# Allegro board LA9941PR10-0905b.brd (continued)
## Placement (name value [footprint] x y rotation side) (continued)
PC270  -  [C_0402]  100.14 24.35 0 bottom
PC271  -  [C_0402]  66.08 23.15 180 top
PC301  -  [C_0402]  48.17 37.17 270 top
PC302  -  [C_0402]  51.47 36.26 90 top
PC303  -  [C_0402]  41.82 22.57 270 bottom
PC304  -  [C_0402]  42.71 22.57 270 bottom
PC305  -  [C_0805]  42.33 22.45 270 top
PC306  -  [C_0402]  43.73 22.57 270 bottom
PC307  -  [C_0603]  49.31 35.89 90 top
PC308  -  [C_0402]  44.62 22.57 270 bottom
PC309  -  [C_0805]  44.11 22.45 270 top
PC310  -  [C_0603]  44.68 32.17 180 top
PC311  -  [C_0603]  54.33 31.25 180 top
PC312  -  [C_B2]  33.92 20.01 90 top
PC313  -  [C_B2]  59.02 21.19 90 bottom
PC314  -  [C_0402]  44.49 16.7 90 top
PC315  -  [C_0402]  41.82 19.14 270 top
PC316  -  [C_0603]  39.03 27.13 270 bottom
PC317  -  [C_0603]  47.47 25.67 180 bottom
PC319  -  [C_0603]  48.92 28.74 0 top
PC320  -  [C_0402]  47.79 29.3 270 top
PC340  -  [C_0402]  45.53 22.57 270 bottom
PC400  -  [C_0805]  130.39 15.3 270 bottom
PC401  -  [C_0805]  130.39 15.3 270 top
PC402  -  [C_0402]  129.07 14.74 270 top
PC403  -  [C_0402]  129.07 14.74 270 bottom
PC404  -  [C_0603]  126.81 14.68 90 bottom
PC405  -  [C_0805]  125.64 21.08 90 bottom
PC406  -  [C_0805]  126.28 20.97 90 top
PC407  -  [C_0603]  127.05 11.95 180 top
PC408  -  [C_B2]  143.57 15.12 90 bottom
PC409  -  [C_0603]  132.9 18.61 180 bottom
PC410  -  [C_0603]  123.61 13.34 270 top
PC411  -  [C_0402]  124.9 20.89 90 top
PC412  -  [C_0402]  121.28 19.87 90 top
PC500  -  [C_0402]  241.12 62.61 270 top
PC501  -  [C_0402]  242.04 62.61 270 top
PC502  -  [C_0805]  240.55 64.85 90 top
PC503  -  [C_0805]  244.29 63.2 90 top
PC504  -  [C_0603]  234.95 65.86 90 top
PC506  -  [C_0603]  232.79 68.59 270 top
PC507  -  [C_B2]  254.44 70.39 270 bottom
PC509  -  [C_0402]  245.4 68.03 180 top
PC510  -  [C_0402]  227.52 68.7 90 bottom
PC511  -  [C_0402]  242.93 62.61 270 top
PC600  -  [C_0402]  184.32 123.74 270 top
PC601  -  [C_0402]  184.21 123.78 270 bottom
PC602  -  [C_0402]  191.2 126.22 180 top
PC603  -  [C_0805]  185.61 123.92 270 top
PC604  -  [C_0603]  187.87 126.25 0 top
PC605  -  [C_0402]  191.37 123.71 0 top
PC607  -  [C_0603]  183.96 119.32 90 top
PC610  -  [C_0805]  185.61 123.92 270 bottom
PC611  -  [C_0805]  186.38 109.98 0 bottom
PC612  -  [C_0805]  186.38 111.69 0 bottom
PC613  -  [C_0805]  186.21 109.99 0 top
PC614  -  [C_0603]  190.56 120.85 270 top
PC620  -  [C_0402]  183.32 123.76 270 bottom
PC621  -  [C_0805]  187.36 123.9 270 top
PC700  -  [C_D2]  121.2 74.56 0 bottom
PC701  -  [C_0805]  112.94 108.05 270 bottom
PC702  -  [C_0805]  114.72 108.05 270 top
PC703  -  [C_0805]  112.94 108.05 270 top
PC704  -  [C_0402]  116.91 108.12 270 top
PC705  -  [C_0402]  116.04 108.12 270 top
PC706  -  [C_0603]  120.01 112.09 0 bottom
PC707  -  [C_0603]  113.28 102.43 90 bottom
PC708  -  [C_0603]  123.97 115.04 270 top
PC709  -  [C_0402]  123.97 121.75 270 bottom
PC710  -  [C_0402]  124.85 122.62 90 bottom
PC711  -  [C_0603]  125.21 113.61 90 top
PC714  -  [C_0603]  127.71 114.89 180 top
PC715  -  [C_0805]  116.24 72.95 90 top
PC716  -  [C_0805]  114.47 72.95 90 top
PC717  -  [C_0805]  118.02 72.95 90 top
PC718  -  [C_0402]  128.97 119.39 0 bottom
PC719  -  [C_0402]  119.42 73.15 90 top
PC721  -  [C_0402]  120.39 73.15 90 top
PC722  -  [C_0402]  128.97 115.65 0 bottom
PC724  -  [C_0402]  126.63 120.84 90 bottom
PC725  -  [C_0402]  128.01 122.96 270 bottom
PC726  -  [C_0402]  126.68 121.66 90 top
PC727  -  [C_0603]  124.78 109.8 90 bottom
PC728  -  [C_0603]  114.43 79.57 270 top
PC729  -  [C_0402]  129.88 113.87 180 bottom
PC730  -  [C_0603]  129.49 109.8 90 bottom
PC731  -  [C_0603]  128.22 109.8 90 bottom
PC732  -  [C_0402]  129.3 116.03 180 top
PC733  -  [C_0402]  127.82 118 270 top
PC734  -  [C_0402]  129.92 116.71 90 bottom
PC736  -  [C_0402]  128.97 117.62 270 bottom
PC737  -  [C_0402]  126.05 115.96 0 top
PC738  -  [C_0402]  126.96 117.11 180 top
PC761  -  [C_0402]  121.36 73.15 90 top
PC762  -  [C_0402]  117.79 108.12 270 top
PC800  -  [C_0603]  145.12 116.8 90 bottom
PC801  -  [C_0805]  153.73 122.78 270 top
PC802  -  [C_0805]  155.88 123.99 0 top
PC803  -  [C_0805]  155.88 122.06 0 top
PC804  -  [C_0805]  153.84 122.02 270 bottom
PC805  -  [C_0402]  152.33 121.88 270 top
PC806  -  [C_0402]  152.45 121.51 270 bottom
PC807  -  [C_0402]  140.04 122.06 0 top
PC809  -  [C_0603]  161.22 122.25 0 top
PC810  -  [C_0402]  140.07 120.91 0 top
PC811  -  [C_0402]  138.24 118.2 270 bottom
PC812  -  [C_0402]  142.37 120.07 90 top
PC813  -  [C_0603]  145.32 127.53 270 bottom
PC814  -  [C_0805]  164.76 126.21 270 top
PC815  -  [C_0805]  166.54 126.21 270 top
PC816  -  [C_0805]  164.76 126.21 270 bottom
PC817  -  [C_0805]  168.31 126.21 270 top
PC818  -  [C_0402]  163.37 126.2 270 bottom
PC819  -  [C_0402]  163.37 126.2 270 top
PC820  -  [C_0402]  136.5 120.35 270 bottom
PC821  -  [C_0402]  137.38 123.96 0 bottom
PC822  -  [C_0603]  169.2 120.73 90 top
PC823  -  [C_0603]  146.53 122.95 0 bottom
PC824  -  [C_0402]  137.38 125.87 0 bottom
PC825  -  [C_0402]  140.96 124.09 180 top
PC829  -  [C_B2]  180.53 113.68 90 bottom
PC830  -  [C_B2]  184.08 113.68 90 bottom
PC831  -  [C_B2]  180.62 117.94 180 bottom
PC832  -  [C_0805]  176.95 126.85 270 top
PC833  -  [C_0805]  173.39 126.85 270 bottom
PC834  -  [C_0805]  173.39 126.85 270 top
PC835  -  [C_0805]  175.17 126.85 270 top
PC836  -  [C_0402]  172 126.96 270 bottom
PC837  -  [C_0402]  172 126.96 270 top
PC838  -  [C_0603]  176.95 121.74 90 top
PC839  -  [C_0603]  182.41 127.71 270 top
PC850  -  [C_0402]  151.48 121.51 270 bottom
PC851  -  [C_0402]  162.43 126.2 270 top
PC852  -  [C_0402]  178.41 127.48 270 top
PC900  -  [C_0402]  154.35 96.05 0 top
PC901  -  [C_0402]  156.38 97.07 0 top
PC902  -  [C_0402]  156.38 98.08 0 top
PC903  -  [C_0402]  162.12 98.08 180 top
PC904  -  [C_0402]  152.32 97.07 0 top
PC905  -  [C_0402]  150.95 98.08 180 top
PC906  -  [C_0402]  159.33 98.08 180 top
PC907  -  [C_0402]  164.15 97.07 180 top
PC908  -  [C_0402]  152.32 96.05 0 top
PC909  -  [C_0402]  150.95 95.03 180 top
PC910  -  [C_0603]  217.02 89.67 0 top
PC911  -  [C_0603]  212 89.67 0 top
PC912  -  [C_0603]  213.53 91.96 180 top
PC913  -  [C_0603]  212.07 93.74 0 top
PC914  -  [C_0603]  213.46 95.77 180 top
PC915  -  [C_0603]  212.07 97.74 0 top
PC916  -  [C_0603]  214.61 89.67 0 top
PC917  -  [C_0603]  215.94 91.96 180 top
PC918  -  [C_0603]  214.48 93.74 0 top
PC919  -  [C_0603]  215.88 95.77 180 top
PC921  -  [C_D2]  129.26 90.73 90 bottom
PC922  -  [C_D2]  133.58 86.57 270 bottom
PC923  -  [C_D2]  144.92 113.88 180 bottom
PC924  -  [C_D2]  128.88 86.57 270 bottom
PC926  -  [C_0402]  152.32 98.08 0 top
PC927  -  [C_0402]  159.33 97.07 180 top
PC928  -  [C_0402]  168.09 97.07 180 top
PC929  -  [C_0402]  162.12 97.07 180 top
PC930  -  [C_0402]  153.47 82.81 0 top
PC931  -  [C_0402]  151.64 82.14 180 top
PC932  -  [C_0402]  156.38 96.05 0 top
PC933  -  [C_0402]  151.64 83.16 180 top
PC934  -  [C_0402]  172.15 97.07 180 top
PC935  -  [C_0402]  154.35 98.08 0 top
PC936  -  [C_0402]  216.97 95.77 0 top
PC937  -  [C_0402]  211.57 88.21 180 top
PC938  -  [C_0402]  218.31 97.59 90 top
PC939  -  [C_0402]  217.44 97.67 180 top
PC940  -  [C_0603]  212.89 87.58 270 top
PC941  -  [C_0603]  217.97 87.58 270 top
PC942  -  [C_0603]  215.43 87.58 270 top
PC943  -  [C_0603]  214.16 87.58 270 top
PC944  -  [C_0603]  216.7 87.58 270 top
PC953  -  [C_0805]  154.21 87.92 0 top
PC954  -  [C_0805]  154.21 85.89 0 top
PC955  -  [C_0805]  154.21 89.95 0 top
PC956  -  [C_0805]  159.77 85.74 180 top
PC958  -  [C_0805]  222.69 96.74 270 top
PC959  -  [C_0805]  222.41 89.99 90 top
PC961  -  [C_0805]  217.42 93.7 270 top
PC962  -  [C_0805]  219.23 91.14 0 top
PC963  -  [C_0805]  221.04 95.64 180 top
PC964  -  [C_0805]  219.37 98.05 0 top
PC965  -  [C_0805]  154.21 94.02 0 top
PC966  -  [C_0805]  154.21 91.99 0 top
PC967  -  [C_0805]  159.77 89.8 180 top
PC968  -  [C_0805]  165.05 86.78 180 top
PC969  -  [C_0805]  165.05 88.56 180 top
PC970  -  [C_0805]  168.53 94.63 180 top
PC971  -  [C_0805]  159.77 93.99 180 top
PC972  -  [C_0805]  165.05 85.07 180 top
PC973  -  [C_0805]  172.04 83.22 180 top
PC974  -  [C_0805]  165.05 90.59 180 top
PC975  -  [C_0805]  165.05 94.65 180 top
PC976  -  [C_0805]  165.05 92.62 180 top
PC977  -  [C_0805]  171.02 87.03 180 top
PC978  -  [C_0805]  171.02 88.94 180 top
PC979  -  [C_0805]  171.02 90.84 180 top
PC980  -  [C_0805]  172.04 92.75 180 top
PC981  -  [C_0805]  172.04 94.78 180 top
PC982  -  [C_0805]  171.02 85.13 180 top
PC983  -  [C_0805]  159.77 87.77 180 top
PC984  -  [C_0805]  159.77 91.96 180 top
PC990  -  [C_0805]  219.23 92.87 0 top
PC991  -  [C_0402]  143.84 111.07 180 bottom
PC992  -  [C_0402]  132.98 95.41 90 bottom
PC993  -  [C_0402]  132.07 95.41 90 bottom
PC994  -  [C_0402]  143.84 110.18 180 bottom
PC995  -  [C_0402]  140.03 90.51 0 bottom
PC996  -  [C_0402]  140.03 89.59 0 bottom
PC997  -  [C_0402]  138.24 82.19 270 bottom
PC998  -  [C_0402]  137.27 82.19 270 bottom
PC999  -  [C_0402]  177.38 110.05 270 bottom
PC1000  -  [C_0402]  178.27 110.05 270 bottom
PC1001  -  [C_0402]  155.83 110.4 180 bottom
PC1002  -  [C_0402]  155.85 111.31 180 bottom
PD100  -  [BAV99W-7-F_SOT323-3]  47.51 40.94 0 bottom
PD102  -  [PESD24VS2UT_SOT23-3]  43.85 49.79 0 bottom
PD103  -  [PESD24VS2UT_SOT23-3]  101.38 18.91 0 top
PD104  -  [PESD24VS2UT_SOT23-3]  97.45 18.91 0 top
PD200  -  [RB751V-40_SOD323-2]  73.39 33.29 0 top
PD201  -  [BAT54HT1G_SOD323-2]  74.33 26.61 270 bottom
PD202  -  [SX34H_SMA2]  97.38 31.57 0 bottom
PH700  -  [R_0402]  116.95 78.19 0 bottom
PH701  -  [R_0402]  125.21 80.2 270 bottom
PJP300  -  [JUMP_43X118]  42.33 26.17 270 top
PJP301  -  [JUMP_43X118]  55.54 24.71 90 bottom
PJP302  -  [JUMP_43X118]  33.72 25.03 90 bottom
PJP303  -  [JUMP_43X118]  55.69 24.22 90 top
PJP400  -  [JUMP_43X118]  132.45 20.86 270 top
PJP401  -  [JUMP_43X39]  128.72 19.52 270 top
PJP402  -  [JUMP_43X79]  128.44 21.6 0 bottom
PJP403  -  [JUMP_43X118]  140.33 17.81 90 top
PJP404  -  [JUMP_43X118]  141.03 19.65 90 bottom
PJP500  -  [JUMP_43X118]  237.81 61.81 90 top
PJP501  -  [JUMP_43X118]  255.72 59.86 180 bottom
PJP502  -  [JUMP_43X118]  251.36 64.92 270 bottom
PJP600  -  [JUMP_43X79]  184.3 126.5 0 bottom
PJP601  -  [JUMP_43X118]  189.96 110.86 0 bottom
PJP602  -  [JUMP_43X118]  189.8 112.66 0 top
PJP700  -  [JUMP_43X118]  116.5 111.05 270 bottom
PJP701  -  [JUMP_43X118]  115.86 69.69 90 bottom
PJP800  -  [JUMP_43X118]  151.25 125.87 0 bottom
PL100  -  [KC_FBMA-L11-201209-221LMA35_2P]  24.69 87.31 0 bottom
PL101  -  [MURAT_BLM15AG102SN1D_2P]  27.37 88.91 90 top
PL102  -  [TAI-T_HCB2012KF-121T50_2P]  99.52 27.25 0 bottom
PL103  -  [KC_FBMA-L11-201209-221LMA35_2P]  31.69 92.31 0 top
PL105  -  [TAI-T_HCB2012KF-121T50_2P]  99.52 25.6 0 bottom
PL106  -  [KC_FBMA-L11-201209-221LMA35_2P]  24.69 85.38 0 bottom
PL108  -  [KC_FBMA-L11-201209-221LMA35_2P]  31.69 90.38 0 top
PL203  -  [CYNTE_PCMB104E-2R2MS_2P]  79.71 16.29 0 bottom
PL205  -  [KC_FBMA-L11-201209-221LMA35_2P]  67.26 19.95 0 bottom
PL206  -  [KC_FBMA-L11-201209-221LMA35_2P]  67.26 18.17 0 bottom
PL300  -  [PANAS_ETQP3W1R5WFN_2P]  49.71 19.79 0 bottom
PL301  -  [TOKO_FDSD0630-H-3R3M-P3_2P]  33.56 20.08 0 bottom
PL400  -  [TOKO_FDSD0630-H-1R0M-P3_2P]  139.87 14.06 180 bottom
PL500  -  [TOKO_FDSD0630-H-1R0M-P3_2P]  245.17 72.83 0 bottom
PL600  -  [PANAS_ETQP3W1R5WFN_2P]  189.29 120.2 270 bottom
PL700  -  [TAI-T_HCB2012KF-121T50_2P]  119.42 71.37 270 bottom
PL701  -  [TOKO_FDUE1040J-H-R36M-P3_4P]  111.95 96.28 0 bottom
PL702  -  [TOKO_FDUE1040J-H-R36M-P3_4P]  111.82 85.48 0 bottom
PL705  -  [TAI-T_HCB2012KF-121T50_2P]  113.07 109.63 90 bottom
PL801  -  [NEC_MPC0740LR42C_2P]  159.93 117.92 270 bottom
PL802  -  [NEC_MPC0740LR42C_2P]  167.55 117.92 270 bottom
PL803  -  [NEC_MPC0740LR42C_2P]  174.92 117.92 270 bottom
PQ100  -  [FDV301N-G_SOT23-3]  42.92 42.24 90 bottom
PQ101  -  [MMST3904-7-F_SOT323-3]  47.1 45.01 180 bottom
PQ102  -  [SI3457CDV-T1-GE3_TSOP6]  116.64 14.28 270 top
PQ103  -  [L2N7002WT1G_SC70-3]  112.46 11.31 180 top
PQ200  -  [MDS1521URH_SO8]  63.16 25.75 180 bottom
PQ201  -  [MDS1521URH_SO8]  61.46 23.27 0 bottom
PQ202  -  [2N7002-7-F_SOT23-3]  67.12 26.68 90 top
PQ203  -  [DMN66D0LDW-7_SOT363-6]  69.57 30.76 270 bottom
PQ204  -  [CSD87351Q5D_SON8-7]  71.64 19.82 90 bottom
PQ207  -  [2N7002KW_SOT323-3]  83.6 26.81 0 bottom
PQ208  -  [AO4407AL_SO8]  92.42 25.42 90 bottom
PQ230  -  [L2N7002WT1G_SC70-3]  58 36.09 180 bottom
PQ231  -  [DMN66D0LDW-7_SOT363-6]  44.5 37.41 270 bottom
PQ300  -  [MDV1528URH_PDFN33-8-5]  37.93 22.88 270 top
PQ301  -  [MDU1516URH_POWERDFN56-8-5]  51.22 23.1 90 top
PQ302  -  [MDV1524URH_PDFN33-8-5]  40.88 17.2 90 top
PQ303  -  [MDU1512RH_POWERDFN56-8-5]  45.88 21.09 270 top
PQ400  -  [MDV1527URH_POWERDFN33-8-5]  134.73 15.62 90 top
PQ401  -  [MDV1522URH_PDFN33-8-5]  131.79 13.66 270 top
PQ500  -  [MDV1528URH_PDFN33-8-5]  247.79 64.74 270 bottom
PQ501  -  [MDV1524URH_PDFN33-8-5]  245.27 66.53 90 bottom
PQ700  -  [CSD87351Q5D_SON8-7]  115.81 107.86 0 bottom
PQ703  -  [CSD87351Q5D_SON8-7]  114.77 73.14 180 bottom
PQ800  -  [CSD87351Q5D_SON8-7]  155.59 122.52 90 bottom
PQ801  -  [CSD87351Q5D_SON8-7]  167.25 126.15 0 bottom
PQ802  -  [CSD87351Q5D_SON8-7]  175.88 126.79 0 bottom
PR101  -  [R_0402]  42.66 39.7 0 bottom
PR102  -  [R_0402]  47.19 39.7 180 bottom
PR103  -  [R_0402]  44.44 39.7 0 bottom
PR104  -  [R_0402]  44.03 45.3 0 bottom
PR105  -  [R_0402]  46.7 43.92 0 bottom
PR106  -  [R_0402]  46.39 48.06 0 bottom
PR107  -  [R_0402]  120.19 10.99 0 top
PR108  -  [R_0402]  114.35 11.88 0 top
PR109  -  [R_0402]  102.4 23.05 90 top
PR110  -  [R_0402]  111.5 15.26 270 top
PR111  -  [R_0402]  100.37 23.05 90 top
PR112  -  [R0402_0OHM]  112.38 14.36 0 top
PR113  -  [R_0402]  98.84 23.18 90 top
PR114  -  [R_0402]  103.54 23.96 270 top
PR116  -  [R_0402]  162.12 12.71 0 top
PR118  -  [R_0402]  162.09 11.85 270 top
PR200  -  [R_0402]  66.94 28.4 0 bottom
PR201  -  [R_2512_4P]  60.72 18.94 90 top
PR202  -  [R_0805]  65.23 29.73 0 top
PR203  -  [R_0805]  65.23 31.51 0 top
PR204  -  [R_0402]  65.7 30.95 270 bottom
PR207  -  [R0603_0OHM]  65.34 25.98 90 bottom
PR208  -  [R_0402]  66.94 27.47 0 bottom
PR209  -  [R0402_0OHM]  79.03 34.12 270 bottom
PR210  -  [R0402_0OHM]  78.14 34.12 270 bottom
PR211  -  [R_0402]  66.59 30.04 90 bottom
PR212  -  [R_0402]  70.55 28.25 90 bottom
PR213  -  [R_1206]  72.39 32.27 270 bottom
PR214  -  [R_0402]  84.06 30.75 180 bottom
PR215  -  [R_0603]  75.41 28.21 180 bottom
PR216  -  [R_0402]  81.77 30.77 180 top
PR217  -  [R_0402]  82.12 34.12 270 bottom
PR218  -  [R0402_0OHM]  79.41 25.41 270 bottom
PR219  -  [R_2512_4P]  88.46 13.2 90 top
PR220  -  [R0402_0OHM]  83.01 34.12 270 bottom
PR221  -  [R0402_0OHM]  80.3 25.41 270 bottom
PR222  -  [R_1206]  78.91 19.63 270 top
PR223  -  [R_0402]  81.23 33.21 90 bottom
PR224  -  [R_0402]  84.06 26.94 180 top
PR225  -  [R_0402]  84.06 24.9 180 top
PR227  -  [R_0402]  92.71 31.39 270 bottom
PR230  -  [R0402_0OHM]  84.06 28.97 180 bottom
PR231  -  [R0402_0OHM]  84.06 28.08 180 bottom
PR280  -  [R0402_0OHM]  113.42 18.8 180 top
PR281  -  [R_0402]  115.2 18.8 180 top
PR282  -  [R_0402]  112.38 15.25 0 top
PR283  -  [R_0402]  116.06 15.5 0 top
PR284  -  [R_0402]  116.97 17.29 270 top
PR290  -  [R_0402]  59.88 33.49 90 bottom
PR291  -  [R_0402]  46.7 37.55 270 bottom
PR292  -  [R_0402]  45.35 38.82 180 bottom
PR293  -  [R_0402]  45.81 36.63 90 bottom
PR294  -  [R_0402]  41.62 37.52 270 bottom
PR300  -  [R_0402]  47.28 37.17 270 top
PR301  -  [R_0402]  52.36 36.26 90 top
PR302  -  [R_0402]  47.21 35.32 0 top
PR304  -  [R_0402]  51.52 35.32 0 top
PR305  -  [R_0402]  43.78 35.06 0 top
PR306  -  [R_0402]  52.92 34.18 0 top
PR307  -  [R_0603]  43.28 30.9 0 top
PR308  -  [R_0603]  52.93 29.98 0 top
PR309  -  [R_1206]  37.38 24.33 90 bottom
PR310  -  [R_1206]  51.66 25.67 180 bottom
PR335  -  [R0402_0OHM]  50.46 36.92 270 top
PR337  -  [R0402_0OHM]  43.78 33.29 0 top
PR338  -  [R0402_0OHM]  46.9 29.3 270 top
PR340  -  [R0402_0OHM]  43.78 34.18 0 top
PR341  -  [R0402_0OHM]  52.92 33.29 0 top
PR350  -  [R_0402]  52.92 32.4 0 top
PR400  -  [R_0603]  126.81 17.34 90 bottom
PR401  -  [R_0402]  124.71 12.19 90 top
PR402  -  [R_0603]  122.34 11.94 90 top
PR403  -  [R_1206]  136.83 18.63 180 bottom
PR405  -  [R_0402]  122.17 19.87 90 top
PR406  -  [R_0402]  121.27 16.01 0 top
PR407  -  [R0402_0OHM]  121.27 17.15 0 top
PR408  -  [R_0402]  122.19 18.93 180 top
PR409  -  [R0402_0OHM]  121.27 18.04 0 top
PR501  -  [R_0603]  232.41 65.35 0 top
PR502  -  [R_0402]  227.49 66.81 0 bottom
PR503  -  [R0402_0OHM]  227.49 67.76 0 bottom
PR504  -  [R_1206]  247.23 64.59 90 top
PR505  -  [R_0402]  229.84 70.18 0 bottom
PR507  -  [R_0402]  228.47 68.7 90 bottom
PR508  -  [R_0402]  226.57 68.7 90 bottom
PR510  -  [R_0603]  234.88 69.22 90 top
PR600  -  [R_0402]  193.65 124.27 90 top
PR602  -  [R_0402]  192.3 126.06 0 top
PR607  -  [R_1206]  185.29 120.34 0 top
PR608  -  [R_0603]  189.29 120.85 270 top
PR700  -  [R_0402]  119.43 118.88 0 top
PR701  -  [R_0402]  119.43 119.83 0 top
PR702  -  [R_0402]  122.17 121.81 270 top
PR703  -  [R0402_0OHM]  119.47 118.88 0 bottom
PR704  -  [R_0402]  119.47 116.22 0 bottom
PR705  -  [R0402_0OHM]  119.47 119.77 0 bottom
PR706  -  [R0402_0OHM]  123.06 121.81 270 top
PR707  -  [R_0402]  119.47 117.11 0 bottom
PR709  -  [R_0402]  119.47 118 0 bottom
PR710  -  [R0402_0OHM]  121.3 121.75 270 bottom
PR711  -  [R_0402]  122.19 123.53 270 bottom
PR712  -  [R0402_0OHM]  123.33 110.3 90 top
PR713  -  [R_0603]  120.14 114.63 270 bottom
PR714  -  [R_0603]  124.75 108.72 270 bottom
PR715  -  [R_0603]  126.02 107.33 90 bottom
PR716  -  [R_1206]  111.63 99.77 90 bottom
PR717  -  [R_0402]  128.01 105.21 90 bottom
PR718  -  [R_0402]  123.06 121.75 270 bottom
PR719  -  [R0402_0OHM]  122.19 121.75 270 bottom
PR721  -  [R_0402]  128.65 107.06 90 bottom
PR722  -  [R_0402]  124.85 121.75 270 bottom
PR724  -  [R_0402]  125.73 121.75 270 bottom
PR725  -  [R0402_0OHM]  125.49 111.21 270 top
PR726  -  [R_0402]  124.85 123.58 270 top
PR727  -  [R_0402]  125.73 123.53 270 bottom
PR728  -  [R_0402]  126.05 118 0 top
PR730  -  [R_0603]  126.76 111.21 270 top
PR732  -  [R_0402]  128.97 121.18 270 bottom
PR733  -  [R_0402]  129.86 121.18 270 bottom
PR734  -  [R_0402]  128.97 114.76 0 bottom
PR736  -  [R_0402]  126.68 119.88 90 top
PR738  -  [R_0402]  128.97 122.04 90 bottom
PR739  -  [R_0402]  130.74 115.65 270 bottom
PR740  -  [R_0603]  126.05 111.2 270 bottom
PR741  -  [R_0603]  124.75 106.18 270 bottom
PR742  -  [R_0603]  126.02 104.79 90 bottom
PR743  -  [R_1206]  114.43 83.38 270 top
PR744  -  [R_0402]  127.13 105.21 90 bottom
PR745  -  [R_0402]  128.97 106.13 270 bottom
PR747  -  [R0402_0OHM]  130.62 110.95 270 bottom
PR748  -  [R_0402]  129.88 112.98 180 bottom
PR749  -  [R_0402]  127.13 110.04 90 bottom
PR801  -  [R_0603]  143.85 118.2 270 bottom
PR803  -  [R_0402]  141.82 117.28 90 bottom
PR804  -  [R_0402]  138.29 121.3 180 bottom
PR806  -  [R_1206]  161.2 118.19 90 top
PR807  -  [R_0402]  138.21 120.36 270 bottom
PR809  -  [R_0402]  140.02 117.28 90 bottom
PR812  -  [R_0402]  140.07 120.02 0 top
PR813  -  [R_0603]  144.06 126.12 90 bottom
PR815  -  [R_0402]  135.63 117.6 90 bottom
PR817  -  [R_0402]  137.12 122.19 0 bottom
PR818  -  [R0402_0OHM]  220.69 76.77 180 top
PR819  -  [R_0402]  173.57 110.07 270 top
PR821  -  [R_0603]  146.53 124.22 0 bottom
PR822  -  [R_1206]  170.09 116.84 90 top
PR823  -  [R0402_0OHM]  220.71 75.83 180 top
PR824  -  [R_0402]  136.52 124.86 270 bottom
PR825  -  [R_0402]  172.66 110.07 270 top
PR827  -  [R_0402]  138.29 126.76 180 bottom
PR830  -  [R_1206]  175.04 118.95 90 top
PR832  -  [R_0603]  181.14 126.31 90 top
PR836  -  [R0402_0OHM]  140.91 117.28 90 bottom
PR837  -  [R_0402]  147.36 121.62 180 bottom
PR841  -  [R_0402]  142.71 118.19 270 bottom
PR842  -  [R_0402]  142.53 126.68 90 bottom
PR850  -  [R_0402]  141.64 127.59 270 bottom
PR851  -  [R_0402]  140.75 127.59 270 bottom
PR852  -  [R_0402]  139.86 127.59 270 bottom
PR853  -  [R0402_0OHM]  183.45 121.83 90 top
PT200  -  [TPC12]  114.31 20.91 0 top
PT601  -  [TPC12]  191.27 122.51 0 top
PU200  -  [BQ24715RGRR_QFN20_3P5X3P5]  78.54 30.57 0 bottom
PU202  -  [INA199A2DCKR_SC70-6]  112.69 17.68 270 top
PU300  -  [TPS51225CRUKR_QFN20_3X3]  49.57 33.92 180 top
PU400  -  [G5616ARZ1U_TQFN20_3X3]  125.93 18.92 180 top
PU500  -  [RT8237EZQW-2_WDFN10_3X3]  229.83 66.89 90 bottom
PU600  -  [TPS51367RVER_QFN28_4P5X3P5]  191.27 122.9 180 bottom
PU700  -  [ISL95812HRZ-T_QFN32_4X4]  123.2 118.26 0 bottom
PU800  -  [RT8813AGQW_WQFN24_4X4]  143.53 120.47 180 bottom
PU801  -  [RT9610BZQW_WDFN8_2X2]  182.53 124.28 180 top
Q11  -  [SSM3K7002FU_SC70-3]  234.32 22.61 90 bottom
Q15  -  [DMN66D0LDW-7_SOT363-6]  18.92 17.11 90 bottom
Q16  -  [DMN66D0LDW-7_SOT363-6]  22.78 15.28 90 bottom
Q17  -  [DMN66D0LDW-7_SOT363-6]  25.76 16.68 90 bottom
Q18  -  [DMN66D0LDW-7_SOT363-6]  25.55 14.83 90 top
Q19  -  [DMN66D0LDW-7_SOT363-6]  17.98 15.46 90 top
Q20  -  [DMN66D0LDW-7_SOT363-6]  27.18 18.01 270 top
QA2  -  [SSM3K7002FU_SC70-3]  3.3 26.42 0 bottom
QA3  -  [2N7002DW-T-R7_SOT363-6]  15.48 39.67 0 bottom
QA4  -  [2N7002DW-T-R7_SOT363-6]  7.84 35.6 270 top
QA5  -  [SSM3K7002FU_SC70-3]  10.54 32.82 270 top
QD1  -  [BSS138-G_SOT23-3]  181.23 69.21 90 bottom
QD2  -  [BSS138-G_SOT23-3]  188.17 69.24 270 bottom
QE1  -  [2N7002_SOT23-3]  181.9 13.03 270 top
QH2  -  [2N7002DW-T-R7_SOT363-6]  247.95 16.93 0 top
QH3  -  [2N7002DW-T-R7_SOT363-6]  248.52 22.21 0 bottom
QH6  -  [2N7002_SOT23-3]  254.67 56.14 270 top
QN2  -  [2N7002DW-T-R7_SOT363-6]  230.1 57.59 90 top
QU3  -  [BSS138-G_SOT23-3]  142.22 67.42 180 bottom
QU7  -  [BSS138-G_SOT23-3]  136.88 67.68 0 bottom
QV7  -  [2N7002DW-T-R7_SOT363-6]  218.78 19.01 270 top
QV21  -  [2N7002DW-T-R7_SOT363-6]  212.36 72.55 180 bottom
QV22  -  [SSM3K7002FU_SC70-3]  229.23 116.79 0 top
QV23  -  [SSM3K7002FU_SC70-3]  213.29 125.74 0 top
QV24  -  [SSM3K7002FU_SC70-3]  251.86 77.96 90 top
QV25  -  [SSM3K7002FU_SC70-3]  254.76 96.72 180 top
QV29  -  [SI3457BDV-T1-E3_TSOP6]  83.18 38.47 270 top
QV30  -  [SSM3K7002FU_SC70-3]  82.36 34.23 90 top
QV37  -  [2N7002_SOT23-3]  14.71 89.4 180 bottom
QV38  -  [SSM3K7002FU_SC70-3]  100.96 45.35 270 bottom
QV39  -  [2N7002_SOT23-3]  201.78 67.6 180 top
QV40  -  [2N7002_SOT23-3]  218.31 74.98 180 top
QV42  -  [2N7002DW-7-F_SOT363-6]  219.38 55.32 0 top
QZ1  -  [SI3456DDV-T1-GE3_TSOP6]  212.85 65.65 0 top
QZ2  -  [2N7002DW-T-R7_SOT363-6]  214.73 60.83 90 top
QZ5  -  [2N7002DW-7-F_SOT363-6]  213.42 59.46 270 top
QZ17  -  [2N7002DW-7-F_SOT363-6]  205.8 67.4 270 top
QZ18  -  [2N7002_SOT23-3]  249.66 52.71 270 top
QZ19  -  [2N7002_SOT23-3]  213.27 55.44 270 top
QZ20  -  [2N7002_SOT23-3]  156.12 13.55 90 bottom
QZ24  -  [2N7002DW-7-F_SOT363-6]  170.09 21.65 90 bottom
QZ25  -  [AO3413_SOT23-3]  244.89 52.78 270 top
R1  -  [R_0402]  198.19 16.58 180 top
R2  -  [R_0402]  207.89 15.59 0 top
R8  -  [R0805_0OHM]  32.57 72.59 90 top
R10  -  [R_0402]  17.66 18.04 180 bottom
R11  -  [R_0402]  22.67 18.52 180 bottom
R12  -  [R_0402]  22.67 17.64 180 bottom
R16  -  [R_0402]  24.83 17.58 180 bottom
R17  -  [R_0402]  24.93 13.22 90 bottom
R18  -  [R_0402]  25.82 13.22 90 bottom
R19  -  [R_0402]  17.66 16.52 180 bottom
R20  -  [R_0402]  23.1 13.22 90 bottom
R21  -  [R_0402]  24.01 13.22 90 bottom
R22  -  [R_0402]  25.54 17.2 180 top
R23  -  [R_0402]  22.67 15.74 90 top
R24  -  [R_0402]  26.22 18.12 180 top
R25  -  [R_0402]  24.14 12.89 90 top
R26  -  [R_0402]  25.08 12.89 90 top
R27  -  [R_0402]  14.03 16.24 0 top
R28  -  [R_0402]  9.14 84.35 90 top
R29  -  [R_0402]  130.79 65.04 90 bottom
R30  -  [R_0402]  229.67 22.93 0 bottom
R31  -  [R_0402]  228.8 22.93 180 bottom
R32  -  [R_0402]  19.9 16.29 180 top
R33  -  [R_0402]  29.55 19.95 270 top
R34  -  [R_0402]  28.66 19.95 270 top
R47  -  [R_0402]  28.18 53.07 90 bottom
R48  -  [R_0402]  29.07 53.07 90 bottom
R51  -  [R_0402]  22.71 74.52 270 top
R52  -  [R_0402]  21.75 74.52 270 top
R53  -  [R0805_0OHM]  260.6 20.55 270 top
R54  -  [R0805_0OHM]  278.8 35.14 90 bottom
R55  -  [R_0805]  278.83 22 270 bottom
R56  -  [R0805_0OHM]  253.96 37.92 180 top
R58  -  [R0805_0OHM]  169.71 108.34 0 bottom
R59  -  [R_0402]  134.72 69.74 90 bottom
R66  -  [R_0402]  25.46 106.18 90 top
R67  -  [R_0402]  25.46 109.43 270 top
R72  -  [R_0402]  208.42 19.53 180 top
R2515  -  [R_0402]  24.73 78.69 0 top
R2530  -  [R_0402]  26.96 79.12 90 top
R2531  -  [R_0402]  26.89 78.24 0 top
R2532  -  [R_0402]  26.33 76.1 270 top
R2533  -  [R_0402]  29.52 74.82 180 top
R2534  -  [R_0402]  31.79 76.67 270 top
R2535  -  [R_0402]  27.28 75.18 90 top
R2536  -  [R_0402]  30.38 74.82 0 top
RA2  -  [R_0402]  13.47 36.2 0 bottom
RA3  -  [R_0402]  9.89 35.64 180 bottom
RA4  -  [R_0402]  6.36 32.9 180 top
RA5  -  [R_0402]  30.64 39.12 180 bottom
RA7  -  [R_0402]  18.01 40.92 270 top
RA9  -  [R_0402]  30.76 38.23 270 top
RA10  -  [R_0402]  29.87 38.23 270 top
RA11  -  [R_0402]  29.87 36.48 270 top
RA17  -  [R_0402]  17.74 38.3 180 top
RA18  -  [R_0402]  17.67 44.69 180 top
RA19  -  [R_0402]  17.65 35.36 90 top
RA20  -  [R_0402]  19.8 44.54 90 bottom
RA22  -  [R_0402]  19.83 40.6 180 top
RA24  -  [R_0402]  32.29 40.04 90 top
RA26  -  [R_0402]  31.43 40.06 180 top
RA33  -  [R0402_0OHM]  26.12 34.81 0 top
RA42  -  [R_0402]  16.57 35.39 270 bottom
RA43  -  [R_0402]  18.35 34.48 90 bottom
RA44  -  [R_0402]  5.46 33.84 90 top
RA45  -  [R_0402]  6.09 30.41 90 bottom
RA46  -  [R_0402]  7.94 33.1 270 bottom
RA47  -  [R_0805]  18.18 32.52 180 bottom
RA48  -  [R_0402]  14.48 30.41 90 bottom
RA49  -  [R_0402]  6.98 32.19 90 bottom
RA50  -  [R_0402]  24.37 25.66 0 top
RA51  -  [R_0402]  12.57 33.1 270 bottom
RA52  -  [R_0402]  13.52 32.19 90 bottom
RA53  -  [R0805_0OHM]  11.54 22.75 270 top
RA54  -  [R_0402]  12.71 35.75 180 top
RA55  -  [R_0402]  6.35 33.84 90 top
RA56  -  [R_0402]  24.37 26.68 0 top
RA57  -  [R_0402]  24.5 28.2 0 top
RA58  -  [R_0402]  24.5 29.22 0 top
RA59  -  [R_0402]  16.6 19.38 0 top
RA60  -  [R_0402]  13.88 26.5 180 top
RA61  -  [R_0402]  13.88 27.41 180 top
RA62  -  [R_0402]  18.02 17.98 0 top
RA63  -  [R_0402]  27.19 23.88 0 top
RA64  -  [R_0402]  18.53 32.6 270 top
RA65  -  [R_0402]  19.42 32.6 270 top
RA66  -  [R_0402]  20.31 32.55 270 top
RA67  -  [R_0402]  17.64 32.6 270 top
RA68  -  [R_0402]  16.62 32.11 270 top
RA70  -  [R_0402]  11.82 34.7 0 top
RA75  -  [R_0402]  18.41 20.28 270 top
RA76  -  [R_0402]  17.64 33.54 0 top
RA81  -  [R_0402]  29.09 27.49 270 top
RA89  -  [R_0402]  26.4 25.79 0 top
RA90  -  [R_0805]  34.33 30.14 270 top
RA91  -  [R_0402]  24.9 33.28 180 top
RA92  -  [R_0402]  15.89 43.76 180 top
RA93  -  [R_0402]  15.89 42.81 180 top
RA94  -  [R_0402]  15.95 40.33 180 top
RA95  -  [R_0402]  15.04 39.38 0 top
RA96  -  [R_0402]  29.81 43.89 0 top
RA97  -  [R_0402]  29.81 45.16 0 top
RA98  -  [R0402_0OHM]  10.96 34.86 90 top
RA99  -  [R_0402]  14.18 35.31 180 bottom
RA100  -  [R_0402]  14.18 34.42 180 bottom
RA101  -  [R0402_0OHM]  17.46 34.48 90 bottom
RA102  -  [R_0402]  15.68 34.48 90 bottom
RD8  -  [R_0402]  174.13 36.52 180 top
RD9  -  [R_0402]  174.13 35.57 180 top
RD15  -  [R_0402]  245.1 34.87 0 top
RD16  -  [R_0402]  243.83 32.27 0 top
RE9  -  [R_0402]  159.66 23.43 0 top
RE11  -  [R_0402]  166.81 24.34 270 top
RE12  -  [R_0402]  160.57 24.32 180 top
RE13  -  [R_0402]  170.61 16.84 0 top
RE20  -  [R_0402]  151.4 17.53 180 top
RE27  -  [R0402_0OHM]  154.87 11.55 90 top
RE28  -  [R_0402]  156.89 15.88 0 top
RE29  -  [R_0402]  154.87 14.24 270 top
RE32  -  [R_0402]  170.61 14.1 0 top
RE33  -  [R_0402]  146.3 23.27 180 top
RE34  -  [R_0402]  146.16 14.92 180 top
RE36  -  [R_0402]  166.81 14.75 270 bottom
RE38  -  [R_0402]  164.78 12.59 270 top
RE39  -  [R_0402]  166.72 11.19 180 top
RE40  -  [R_0402]  165.81 12.08 0 top
RE42  -  [R_0402]  151.13 18.28 90 bottom
RE43  -  [R_0402]  164.72 24.28 270 top
RE44  -  [R_0402]  185.86 13.39 90 top
RE47  -  [R_0402]  177.05 13.15 180 top
RE48  -  [R_0402]  176.13 14.42 0 top
RE49  -  [R_0402]  177.04 12.15 270 top
RE50  -  [R_0402]  185.86 11.49 90 top
RE51  -  [R_0402]  27.1 70.88 180 bottom
RE52  -  [R_0402]  169.07 23.2 270 bottom
RE53  -  [R_0402]  28.24 68.14 0 bottom
RE54  -  [R_0402]  173.8 21.78 90 bottom
RE55  -  [R_0402]  194.83 11.88 180 top
RE56  -  [R_0402]  169.49 24.33 180 top
RE57  -  [R_0402]  171.52 15.95 180 top
RE58  -  [R_0402]  157.96 16.01 180 bottom
RE59  -  [R_0402]  180.02 11.49 90 top
RE60  -  [R0402_0OHM]  169.49 23.44 180 top
RE61  -  [R_0402]  168.03 22.28 90 bottom
RE62  -  [R_0402]  21.21 54 0 bottom
RE63  -  [R_0402]  20.33 54.01 270 bottom
RE64  -  [R_0402]  145.39 22.36 0 top
RE65  -  [R_0402]  17.62 80.78 0 top
RE66  -  [R_0402]  146.37 12.78 270 top
RE68  -  [R_0402]  17.62 79.83 0 top
RE69  -  [R_0402]  194.83 15.31 180 top
RE71  -  [R_0402]  194.83 14.1 180 top
RE72  -  [R_0402]  194.83 17.03 180 top
RE74  -  [R_0402]  144.13 20.07 0 bottom
RE76  -  [R_0402]  167.7 24.34 270 top
RE84  -  [R_0402]  174.81 22.69 270 bottom
RE321  -  [R0402_0OHM]  170.61 13.22 0 top
RE322  -  [R0402_0OHM]  191.4 18.74 180 top
RE340  -  [R_0402]  180.14 17.6 0 top
RE341  -  [R_0402]  180.02 13.33 90 top
RE469  -  [R_0402]  94.4 33.46 180 bottom
RH1  -  [R_0402]  277.65 21.73 180 top
RH2  -  [R_0402]  278.06 24.6 270 top
RH3  -  [R_0402]  261.49 49.1 90 bottom
RH4  -  [R_0402]  262.51 49.1 90 bottom
RH5  -  [R_0402]  278.69 34.76 270 top
RH6  -  [R_0402]  278.71 32.84 180 top
RH7  -  [R_0402]  279.16 29.6 180 bottom
RH8  -  [R_0402]  279.16 30.55 180 bottom
RH11  -  [R_0402]  279.6 31 180 top
RH12  -  [R_0402]  256.91 18.32 270 bottom
RH13  -  [R_0402]  279.84 25.47 90 top
RH14  -  [R_0402]  257.83 16.53 270 bottom
RH15  -  [R_0402]  279.6 31.89 180 top
RH16  -  [R_0402]  280.73 25.47 90 top
RH17  -  [R_0402]  254.35 28.42 0 top
RH18  -  [R_0402]  262.59 15.62 90 bottom
RH19  -  [R_0402]  261.64 15.62 90 bottom
RH20  -  [R_0402]  260.68 15.62 90 bottom
RH21  -  [R_0402]  255.27 23.43 180 top
RH23  -  [R_0402]  275.38 31.89 0 top
RH24  -  [R_0402]  262.59 18.31 270 bottom
RH25  -  [R_0402]  261.64 18.31 270 bottom
RH26  -  [R_0402]  260.68 18.31 270 bottom
RH27  -  [R_0402]  140.13 93.86 0 bottom
RH28  -  [R_0402]  259.9 43.42 90 bottom
RH29  -  [R_0402]  256.03 18.32 270 bottom
RH30  -  [R_0402]  166.23 99.83 0 top
RH31  -  [R_0402]  166.83 107.96 180 bottom
RH32  -  [R_0402]  279.16 31.5 180 bottom
RH33  -  [R_0402]  251.09 15.7 180 bottom
RH35  -  [R_0402]  265.49 21.47 90 top
RH37  -  [R_0402]  273.82 26.3 180 top
RH38  -  [R_0402]  251.09 12.97 180 bottom
RH40  -  [R_0402]  251.09 13.86 180 bottom
RH41  -  [R_0402]  250.17 14.75 0 bottom
RH53  -  [R_0402]  274.32 13.16 270 top
RH62  -  [R_0402]  271.97 42.54 90 bottom
RH63  -  [R_0402]  273.43 13.16 270 top
RH64  -  [R_0402]  263.56 16.53 270 bottom
RH65  -  [R_0402]  275.21 13.16 270 top
RH66  -  [R_0402]  277.73 35.77 0 top
RH67  -  [R_0402]  277.73 36.65 0 top
RH68  -  [R_0402]  253.18 21.29 180 bottom
RH69  -  [R_0402]  253.18 22.18 180 bottom
RH75  -  [R_0402]  254.35 29.33 0 top
RH84  -  [R_0402]  263.58 18.32 270 bottom
RH89  -  [R_0402]  262.68 42.56 0 bottom
RH97  -  [R_0402]  278.42 37.88 90 bottom
RH98  -  [R_0402]  277.74 38.43 0 top
RH99  -  [R_0402]  254.35 30.24 0 top
RH113  -  [R_0402]  252.48 34.62 0 bottom
RH119  -  [R_0402]  278.95 25.47 90 top
RH120  -  [R_0402]  254.32 21.6 0 top
RH121  -  [R_0402]  279.79 22.75 180 top
RH122  -  [R_0402]  278.06 25.47 90 top
RH127  -  [R_0402]  274.51 17.27 90 top
RH130  -  [R_0402]  264.53 21.47 90 top
RH132  -  [R_0402]  273.82 36.65 180 top
RH136  -  [R_0402]  254.32 22.49 0 top
RH138  -  [R_0402]  271.52 39.4 270 top
RH143  -  [R_0402]  273.41 30.81 0 top
RH144  -  [R_0402]  278.66 39.32 180 top
RH145  -  [R_0402]  270.95 43.45 270 bottom
RH146  -  [R_0402]  278.66 37.54 180 top
RH154  -  [R_0402]  241.15 43.97 270 top
RH155  -  [R_0402]  257.67 12.01 270 top
RH158  -  [R_0402]  264.54 17.39 90 bottom
RH159  -  [R_0402]  255.28 27.44 180 top
RH162  -  [R_0402]  253.36 18.31 270 bottom
RH163  -  [R_0402]  279.28 23.95 180 bottom
RH164  -  [R_0402]  256.36 52.84 90 top
RH165  -  [R_0402]  263.83 20.34 180 top
RH167  -  [R_0402]  279.16 32.46 180 bottom
RH168  -  [R_0402]  279.28 24.84 180 bottom
RH169  -  [R_0402]  263.2 22.63 270 top
RH170  -  [R_0402]  270.44 24.64 90 top
RH171  -  [R_0402]  252.27 20.39 0 bottom
RH172  -  [R_0402]  278.37 23.06 0 bottom
RH173  -  [R_0402]  276.35 9.91 90 top
RH174  -  [R_0402]  254.3 20.71 0 top
RH175  -  [R_0402]  255.22 19.82 180 top
RH176  -  [R_0402]  258.78 15.62 90 bottom
RH177  -  [R_0402]  279.16 28.71 180 bottom
RH178  -  [R_0402]  258.81 15.53 90 top
RH180  -  [R_0402]  259.73 15.62 90 bottom
RH188  -  [R_0402]  259.73 17.4 90 bottom
RH191  -  [R_0402]  258.78 17.4 90 bottom
RH193  -  [R_0402]  240.65 15 180 top
RH194  -  [R_0402]  257.83 17.4 90 bottom
RH201  -  [R_0603]  257.68 42.37 180 top
RH202  -  [R0805_0OHM]  265.7 42.58 270 top
RH213  -  [R0805_0OHM]  267.33 46.01 270 bottom
RH219  -  [R_0603]  267.26 42.18 270 top
RH220  -  [R_0603]  268.09 21.61 270 top
RH243  -  [R_0402]  262.12 21.72 90 top
RH244  -  [R_0402]  274.24 24.96 0 top
RH245  -  [R_0402]  255.14 17.4 90 bottom
RH247  -  [R_0402]  255.08 53.68 270 top
RH322  -  [R_0402]  259.7 39.7 0 top
RH416  -  [R0402_0OHM]  259.4 55.2 180 top
RH448  -  [R_0402]  273.21 16.8 270 top
RH456  -  [R_0402]  272.32 16.8 270 top
RH724  -  [R_0402]  270.52 16.8 270 top
RH725  -  [R_0402]  271.42 16.8 270 top
RI6  -  [R_0402]  31.2 61.23 0 top
RI8  -  [R_0402]  27.72 105.43 180 bottom
RI9  -  [R_0402]  27.72 106.57 180 bottom
RI17  -  [R_0402]  21.21 52.15 0 bottom
RI19  -  [R_0402]  21.21 54.88 0 bottom
RI30  -  [R_0402]  17.62 78.18 0 top
RI32  -  [R_0402]  22.39 81.43 270 top
RI74  -  [R0805_0OHM]  26.06 64.24 0 bottom
RI320  -  [R_0402]  28.93 56.55 270 top
RI460  -  [R_0402]  30.83 56.55 270 top
RI461  -  [R_0402]  29.88 56.55 270 top
RI462  -  [R_0402]  27.98 56.55 270 top
RI463  -  [R_0402]  27.09 56.55 270 top
RI464  -  [R_0402]  29.27 66.68 90 top
RI465  -  [R_0402]  28.38 66.68 90 top
RI466  -  [R_0402]  26.6 66.68 90 top
RI467  -  [R_0402]  27.49 66.68 90 top
RI468  -  [R_0402]  24.18 61.35 180 top
RM12  -  [R_0402]  280.48 37.61 270 top
RN1  -  [R_0402]  276.1 12.25 90 top
RN3  -  [R_0402]  33.92 31.07 270 bottom
RN4  -  [R_0402]  35.72 31.07 270 bottom
RN5  -  [R0402_0OHM]  124.27 21.99 270 bottom
RN6  -  [R_0402]  34.83 31.07 270 bottom
RN7  -  [R_0402]  117.16 21.08 90 bottom
RN8  -  [R_0402]  118.93 21.99 270 bottom
RN9  -  [R0402_0OHM]  119.81 21.08 90 bottom
RN10  -  [R_0402]  34.33 39.73 270 bottom
RN11  -  [R_0402]  37.87 39.73 270 bottom
RN12  -  [R_0402]  36.09 39.73 270 bottom
RN13  -  [R_0402]  36.99 39.73 270 bottom
RN14  -  [R_0402]  35.22 39.73 270 bottom
RN15  -  [R_0402]  39.66 38.82 180 bottom
RN16  -  [R_0402]  39.66 39.73 180 bottom
RN17  -  [R_0402]  33.01 31.07 270 bottom
RN18  -  [R_0402]  33.41 38.82 90 bottom
RN19  -  [R_0402]  39.14 32.78 0 bottom
RN20  -  [R_0402]  36.64 31.07 270 bottom
RN21  -  [R_0402]  39.15 31.88 0 bottom
RN23  -  [R_0402]  231.65 57.97 90 top
RN26  -  [R_0402]  226.95 58.5 270 top
RN30  -  [R_0402]  39.17 31 0 bottom
RN33  -  [R_0402]  231.46 61.65 90 top
RN40  -  [R_0402]  40.52 38.84 90 bottom
RN42  -  [R_0402]  39.48 30.11 180 bottom
RPE2  -  [RP_0804_8P4R]  176.15 15.83 180 top
RPH1  -  [RP_0804_8P4R]  279.47 29.92 0 top
RPH2  -  [RP_0804_8P4R]  278.06 26.05 0 bottom
RPH4  -  [RP_0804_8P4R]  277.48 15.29 180 top
RPH5  -  [RP_0804_8P4R]  244.17 14.55 90 top
RPH7  -  [RP_0804_8P4R]  270.06 10.24 90 top
RPH8  -  [RP_0804_8P4R]  250.76 26.29 0 top
RPH9  -  [RP_0804_8P4R]  268.31 12.17 180 top
RPH12  -  [RP_0804_8P4R]  220.5 79.35 270 top
RPH13  -  [RP_0804_8P4R]  219.25 65.61 270 top
RPH14  -  [RP_0804_8P4R]  252.27 17.98 270 top
RPH15  -  [RP_0804_8P4R]  219.25 63.31 90 bottom
RPH16  -  [RP_0804_8P4R]  273.31 43.06 0 top
RPH19  -  [RP_0804_8P4R]  156.78 18.54 0 top
RPH24  -  [RP_0804_8P4R]  265.8 16.57 90 top
RPH25  -  [RP_0804_8P4R]  260.08 15.43 90 top
RPH27  -  [RP_0804_8P4R]  248.88 34.78 180 top
RPH29  -  [RP_0804_8P4R]  269.86 17.33 270 bottom
RPH30  -  [RP_0804_8P4R]  265.8 17.71 270 bottom
RPH32  -  [RP_0804_8P4R]  222.91 63.26 90 bottom
RPH33  -  [RP_0804_8P4R]  219.34 73.86 270 bottom
RT1  -  [R_0402]  191.42 80.91 0 top
RT2  -  [R_0402]  116.04 123.2 0 bottom
RT3  -  [R_0402]  186.81 62.5 90 bottom
RT4  -  [R_0402]  250.69 123.14 180 bottom
RT5  -  [R_0402]  106.21 53.53 90 bottom
RT6  -  [R_0402]  190.74 128.03 180 bottom
RTCD1  -  [BAT54CW_SOT323-3]  256.89 59.44 270 top
RTCR1  -  [R_0402]  253.93 60.22 270 top
RU1  -  [R_0402]  175.5 85.93 180 top
RU2  -  [R_0402]  175.5 87.26 180 top
RU7  -  [R_0402]  144.29 109.89 180 top
RU11  -  [R_0402]  136.47 100.88 180 bottom
RU12  -  [R_0402]  131.81 109.23 180 top
RU13  -  [R_0402]  135.55 98.84 0 bottom
RU30  -  [R_0402]  136.92 103 180 bottom
RU32  -  [R_0402]  137.84 103 0 bottom
RU33  -  [R_0402]  136.47 101.8 180 bottom
RU35  -  [R_0402]  131.81 110.88 180 top
RU36  -  [R_0402]  143.98 113.01 0 top
RU37  -  [R0402_0OHM]  140.85 96.97 180 bottom
RU40  -  [R_0402]  173.09 92.04 90 top
RU42  -  [R_0402]  136.44 110.66 0 bottom
RU43  -  [R0402_0OHM]  137.41 69.73 90 bottom
RU44  -  [R_0402]  173.09 94.73 270 top
RU45  -  [R_0402]  254.25 17.39 90 bottom
RU48  -  [R_0402]  135.55 99.86 0 bottom
RU50  -  [R_0402]  131.67 65.04 90 bottom
RU51  -  [R_0402]  130.79 67.86 270 bottom
RU53  -  [R0402_0OHM]  136.12 62.75 90 bottom
RU54  -  [R_0402]  137.01 62.75 90 bottom
RU56  -  [R_0402]  138.3 69.73 90 bottom
RU58  -  [R_0402]  140.12 77.53 180 top
RU59  -  [R_0402]  140.12 78.62 180 top
RU60  -  [R_0402]  135.61 70.65 270 bottom
RU61  -  [R_0402]  140.12 76.45 180 top
RU62  -  [R_0402]  139.62 65.41 0 bottom
RU66  -  [R_0402]  140.85 95.96 180 bottom
RU67  -  [R_0402]  140.13 94.81 0 bottom
RU68  -  [R_0402]  136.44 107.61 0 bottom
RU72  -  [R_0402]  144.71 64.45 90 bottom
RU73  -  [R_0402]  143.76 65.36 270 bottom
RU74  -  [R_0402]  144.71 69.34 90 bottom
RU76  -  [R_0402]  129.9 66.94 90 bottom
RU77  -  [R_0402]  149.14 90.93 90 top
RU83  -  [R_0402]  185.74 80.59 180 top
RU84  -  [R_0402]  184.83 81.61 0 top
RU85  -  [R_0402]  140.22 105.57 180 bottom
RU86  -  [R_0402]  137.36 106.59 180 bottom
RU87  -  [R_0402]  139.18 106.95 180 bottom
RU90  -  [R_0402]  141.08 98.36 180 bottom
RU91  -  [R_0402]  138.35 99.96 0 bottom
RU93  -  [R_0402]  140.13 99.96 0 bottom
RU94  -  [R_0402]  168.67 107.96 180 bottom
RU96  -  [R_0402]  146.14 108.9 180 top
RU99  -  [R_0402]  144.37 108.9 180 top
RU115  -  [R_0402]  136.44 105.58 0 bottom
RU118  -  [R_0402]  150.07 85.44 270 top
RV5  -  [R_0402]  18.5 110.17 90 bottom
RV8  -  [R0402_0OHM]  230.57 73.85 90 bottom
RV10  -  [R_0402]  215.9 70.63 270 top
RV11  -  [R_0402]  91.81 32.6 270 bottom
RV12  -  [R_0402]  87.77 28.46 180 bottom
RV286  -  [R_0402]  205.96 100.49 180 top
RV289  -  [R_0402]  200.57 69.53 90 top
RV290  -  [R_0402]  199.2 103.23 180 bottom
RV299  -  [R_0402]  215.29 73.85 90 bottom
RV300  -  [R_0402]  216.15 72.66 270 bottom
RV301  -  [R_0402]  222.25 72.85 270 bottom
RV302  -  [R_0402]  222.31 68.66 270 top
RV303  -  [R_0402]  224.13 68.67 270 top
RV304  -  [R_0402]  222.69 73.85 90 top
RV305  -  [R_0402]  223.58 73.85 90 top
RV306  -  [R_0402]  220.53 68.66 270 top
RV307  -  [R_0402]  217.87 68.66 270 top
RV308  -  [R_0402]  223.26 71.01 270 bottom
RV309  -  [R_0402]  222.25 73.85 90 bottom
RV310  -  [R_0402]  221.42 67.75 90 top
RV311  -  [R_0402]  223.24 67.75 90 top
RV312  -  [R_0402]  222.69 71.94 90 top
RV313  -  [R_0402]  223.58 71.94 90 top
RV314  -  [R_0402]  219.64 67.75 90 top
RV315  -  [R_0402]  218.76 67.75 90 top
RV316  -  [R_0402]  223.26 72.85 270 bottom
RV318  -  [R_0402]  223.26 74.76 270 bottom
RV319  -  [R_0402]  216.18 73.85 90 bottom
RV320  -  [R_0402]  198.11 79.32 0 bottom
RV323  -  [R_0402]  199.02 80.21 180 bottom
RV324  -  [R_0402]  198.89 83.7 180 bottom
RV325  -  [R_0402]  215.64 77.3 270 top
RV326  -  [R_0402]  214.74 78.18 0 top
RV327  -  [R_0402]  222.01 87.57 180 top
RV328  -  [R_0402]  219.96 86.25 180 top
RV329  -  [R_0402]  219.96 85.36 180 top
RV330  -  [R_0402]  229.61 74.76 270 bottom
RV331  -  [R_0402]  215.26 72.66 270 bottom
RV332  -  [R_0402]  228.66 73.85 90 bottom
RV333  -  [R_0402]  222.77 21.23 180 top
RV334  -  [R_0402]  217.42 18.56 270 top
RV337  -  [R0603_0OHM]  223.9 82.68 270 top
RV338  -  [R_0402]  202.6 114.41 180 top
RV339  -  [R_0402]  218.37 116.99 270 top
RV340  -  [R_0402]  202.68 115.39 0 top
RV341  -  [R_0402]  222.87 112.34 0 bottom
RV342  -  [R_0402]  224.8 98.75 180 top
RV343  -  [R_0402]  224 99.63 90 top
RV344  -  [R_0402]  218.12 102.7 270 top
RV345  -  [R_0402]  212.98 99.69 90 top
RV346  -  [R_0402]  223.76 87.96 0 top
RV347  -  [R_0402]  224.01 94.43 0 top
RV348  -  [R_0402]  220.79 127.34 270 top
RV349  -  [R_0402]  221.68 127.34 270 top
RV352  -  [R_0402]  221.99 111.44 90 bottom
RV353  -  [R_0402]  223.98 121.17 180 top
RV354  -  [R_0402]  211.65 126.89 270 bottom
RV355  -  [R_0402]  228.51 121.74 0 top
RV356  -  [R_0402]  219.9 128.22 180 top
RV357  -  [R_0402]  228.33 115.45 0 top
RV358  -  [R_0402]  227.32 116.4 0 top
RV359  -  [R_0402]  228.33 114.56 0 top
RV360  -  [R_0402]  227.33 115.46 270 top
RV361  -  [R_0402]  201.92 128.02 270 top
RV362  -  [R_0402]  202.79 128.03 270 top
RV363  -  [R_0402]  202.61 112.28 0 bottom
RV365  -  [R_0402]  193.64 126.94 270 bottom
RV366  -  [R_0402]  201.02 128.04 270 top
RV368  -  [R_0402]  209.79 124.28 0 top
RV369  -  [R_0402]  205.55 128.04 270 top
RV370  -  [R_0402]  209.79 125.17 0 top
RV371  -  [R_0402]  210.7 126.06 180 top
RV372  -  [R_0402]  211.58 126.07 270 top
RV373  -  [R_0402]  210.68 126.94 0 top
RV374  -  [R_0402]  255.19 85.95 180 top
RV375  -  [R_0402]  255.19 86.84 180 top
RV378  -  [R_0402]  238.38 85.66 90 bottom
RV379  -  [R_0402]  251.76 88.04 180 top
RV380  -  [R_0402]  254.13 76.39 90 bottom
RV381  -  [R_0402]  247.95 77.73 270 bottom
RV382  -  [R_0402]  253.91 78.91 180 top
RV383  -  [R_0402]  249.67 76.27 0 top
RV384  -  [R_0402]  250.32 94.57 270 top
RV385  -  [R_0402]  253.91 77.96 180 top
RV386  -  [R_0402]  255.69 78.91 180 top
RV387  -  [R_0402]  254.87 104.5 180 top
RV388  -  [R_0402]  254.87 103.61 180 top
RV389  -  [R_0402]  239.27 104.35 270 bottom
RV391  -  [R_0402]  252.16 114.43 0 bottom
RV392  -  [R_0402]  251.79 105.29 180 top
RV394  -  [R_0402]  251.62 114 90 top
RV395  -  [R_0402]  254.85 102.71 0 top
RV396  -  [R_0402]  253.45 113.04 270 top
RV397  -  [R_0402]  252.63 114.84 0 top
RV398  -  [R_0402]  254.81 100.34 0 top
RV399  -  [R_0402]  254.82 98.48 90 top
RV403  -  [R_0402]  87.82 33.61 270 bottom
RV405  -  [R_0402]  63.26 37.85 90 bottom
RV408  -  [R_0402]  86.56 33.54 180 bottom
RV409  -  [R_0402]  240.45 102.6 270 top
RV410  -  [R_0402]  239.27 86.57 270 bottom
RV411  -  [R0402_0OHM]  34.15 50.12 90 bottom
RV412  -  [R_0402]  88.2 37.14 90 top
RV413  -  [R_0402]  83.64 35.19 180 top
RV414  -  [R_0402]  241.34 104.38 270 top
RV415  -  [R0402_0OHM]  65.87 36.93 180 bottom
RV416  -  [R_0402]  221.87 19.24 0 top
RV417  -  [R_0402]  37.86 43.51 0 top
RV418  -  [R_0402]  239.2 88.07 90 bottom
RV419  -  [R_0402]  221.87 20.26 0 top
RV424  -  [R_0402]  37.86 44.7 0 top
RV429  -  [R_0402]  34.68 99.7 180 top
RV430  -  [R_0402]  33.78 101.05 270 bottom
RV431  -  [R_0402]  33.78 102.83 270 bottom
RV444  -  [R_0402]  29.84 105.75 270 top
RV445  -  [R_0402]  24.31 102.24 0 top
RV447  -  [R_0402]  24.31 101.29 0 top
RV448  -  [R_0402]  34.67 102.83 270 bottom
RV449  -  [R_0402]  34.67 101.05 270 bottom
RV450  -  [R_0402]  35.56 102.83 270 bottom
RV451  -  [R_0402]  35.56 101.05 270 bottom
RV452  -  [R_0402]  14.77 94.2 270 bottom
RV453  -  [R_0402]  11.3 91.05 90 bottom
RV456  -  [R_0402]  11.27 90.06 0 bottom
RV458  -  [R_0402]  34.68 100.91 180 top
RV459  -  [R_0402]  25.21 100.35 270 top
RV460  -  [R_0402]  24.26 99.44 90 top
RV469  -  [R_0402]  97.86 44.65 180 bottom
RV470  -  [R_0402]  100.19 47.06 0 bottom
RV479  -  [R_0402]  207.96 85.36 270 top
RV480  -  [R0402_0OHM]  72.88 36.08 0 bottom
RV481  -  [R0402_0OHM]  89.74 34.04 180 bottom
RV482  -  [R0402_0OHM]  89.74 34.93 180 bottom
RV490  -  [R_0402]  19.66 94.26 270 bottom
RV491  -  [R_0402]  20.55 94.26 270 bottom
RV501  -  [R_0402]  231.52 73.85 90 bottom
RV503  -  [R0402_0OHM]  214.37 74.76 270 bottom
RV505  -  [R_0402]  213.49 74.76 270 bottom
RV506  -  [R_0402]  196.89 61.53 0 bottom
RV507  -  [R_0402]  198.72 63.36 270 bottom
RV508  -  [R_0402]  193.71 71.02 270 bottom
RV509  -  [R_0402]  194.98 71.02 270 bottom
RV510  -  [R0402_0OHM]  229.64 109.68 0 top
RZ3  -  [R_0402]  211.52 60.57 90 top
RZ5  -  [R_0402]  211.66 68.46 180 bottom
RZ6  -  [R_0603]  207.07 64.84 180 top
RZ8  -  [R_0402]  216.09 61.4 90 top
RZ9  -  [R_0402]  243.71 56.79 270 top
RZ10  -  [R_0402]  217.24 59.51 180 top
RZ11  -  [R_0402]  204.15 72.16 270 top
RZ12  -  [R_0402]  212.41 59.65 270 top
RZ15  -  [R_0402]  206.93 68.52 0 top
RZ30  -  [R_0402]  225.74 11.62 90 bottom
RZ38  -  [R_0402]  2.84 27.63 0 bottom
RZ472  -  [R_0402]  242.76 55.87 90 top
RZ484  -  [R_0402]  249.73 50.17 0 top
RZ485  -  [R_0402]  247.95 56.08 0 top
RZ600  -  [R_0402]  255.79 49.92 180 top
RZ601  -  [R_0402]  253.95 49.92 180 top
RZ602  -  [R_0603]  257.34 52.84 0 top
SW1  -  [SW_TML-3WWW-Q-T-R_6P]  21.8 111.67 270 top
SW2  -  [SW_NTC311-EA1T-A160T_4P]  3.17 33.72 270 top
T6  -  [TPC12]  264.43 23.71 0 top
T7  -  [TPC12]  262.64 23.86 0 top
T8  -  [TPC12]  276.72 25.69 180 bottom
T11  -  [TPC12]  199.17 82.37 90 bottom
T12  -  [TPC12]  199.3 84.71 90 bottom
T13  -  [TPC12]  197.12 84.79 90 bottom
T37  -  [TPC12]  279.38 18.81 180 bottom
T38  -  [TPC12]  272.73 22.56 0 top
T39  -  [TPC12]  266.97 22.61 0 top
T40  -  [TPC12]  163.84 12.8 0 top
T41  -  [TPC12]  171.16 19.87 0 top
T42  -  [TPC12]  169.63 14.36 0 top
T43  -  [TPC12]  280.73 35.47 0 top
T44  -  [TPC12]  171.16 15.01 0 top
T46  -  [TPC12]  268.41 23.17 0 top
T81  -  [TPC12]  271.79 19.46 180 bottom
T118  -  [TPC12]  23.3 98.7 90 top
T126  -  [TPC12]  162.93 13.37 0 top
T170  -  [TPC12]  274.02 21.8 0 top
T171  -  [TPC12]  163.57 17.15 180 bottom
T172  -  [TPC12]  175.04 108.15 180 bottom
T173  -  [TPC12]  179.87 107.81 180 bottom
T174  -  [TPC12]  200.65 83.38 180 bottom
T175  -  [TPC12]  271.46 23.76 0 top
T176  -  [TPC12]  167.5 21.96 0 top
T177  -  [TPC12]  274.51 19.34 0 top
T178  -  [TPC12]  161.68 17.28 180 bottom
U1  -  [AT97SC3204-X2A14-AB_TSSOP28]  199.86 20.13 270 top
U4  -  [NCT3705U-A_SOT23-5]  93.12 43.95 270 top
U5  -  [APX9131AAI-TRG_SOT23-3]  4.33 84.67 270 top
U6  -  [HASWELL_BGA_1364P-T]  180.23 104.64 0 bottom
U7  -  [LYNXPOINT_BGA_695P-T]  275.12 21.66 90 bottom
U11  -  [PS8330BQFN48GTR-A0_QFN48_7X7]  25.33 75.56 90 bottom
U12  -  [ALC5505_QFN48_7X7]  22.4 23.23 90 top
U15  -  [ALC3661-CG_MQFN48_6X6]  27.93 39.59 90 top
U22  -  [PS8201ATQFN40GTR2A0_TQFN40_5X5]  27.77 97.41 0 top
U23  -  [W25X20AVSNIG_SO8]  197.46 63.15 180 bottom
UA2  -  [MAX9892ERTLFT_UCSP_6P]  12.18 35.12 180 bottom
UA5  -  [TPA3113D2PWPR_HTSSOP28]  5.62 28.4 0 bottom
UE1  -  [KB9012BF-A3_LFBGA_128P]  161.78 14.66 90 top
UE2  -  [SN74LVC1G06DCKR_SC70-5]  152.35 17.71 90 bottom
UE36  -  [KC3810_QFN24_4X4]  148.66 17.55 90 top
UH2  -  [W25Q64FVSSIG_SO8]  248.47 15.7 270 bottom
UH3  -  [MC74VHC1G08DFT2G_SC70-5]  239.6 13.78 180 top
UH4  -  [SN74AHC1G08DCKR_SC70-5]  244.71 42.67 90 top
UH5  -  [SN74AHC1G08DCKR_SC70-5]  263.53 9.98 90 top
UI5  -  [PS8723BTQFN32GTR-A0_TQFN32_3X6]  29.45 59.55 90 top
UN1  -  [PS8520BTQFN20GTR2_TQFN20_4X4]  37.18 36.06 270 bottom
UN2  -  [LNG3DMTR_LGA16_3X3]  225.98 64 270 top
UN3  -  [APL3512ABI-TRG_SOT23-5]  65.32 33.16 90 bottom
US1  -  [TPS2543RTER_QFN16_3X3]  25.91 51.36 180 bottom
US2  -  [TPS2543RTER_QFN16_3X3]  23.09 76.66 90 top
UU2  -  [SN74LVC1G07DCKR_SC70-5]  132.82 103.02 0 bottom
UU3  -  [74AHC1G09GW_TSSOP5]  132.18 67.13 90 bottom
UV1  -  [N13M_FCBGA_908P]  230 78.2 90 bottom
UV5  -  [K4G41325FC-HC04_FBGA_170P]  226.7 115.67 90 bottom
UV6  -  [K4G41325FC-HC04_FBGA_170P]  208.67 115.67 90 bottom
UV9  -  [K4G41325FC-HC04_FBGA_170P]  242.59 80.44 0 bottom
UV10  -  [K4G41325FC-HC04_FBGA_170P]  242.59 98.48 0 bottom
UV12  -  [APL3512ABI-TRG_SOT23-5]  61.99 40 270 bottom
UZ1  -  [SI4634DY-T1-GE3_SO8]  205.29 63.13 90 bottom
UZ4  -  [TPS22966DPUR_SON14_2X3]  37.46 42.86 180 bottom
UZ14  -  [APL3512ABI-TRG_SOT23-5]  224.42 13.47 270 bottom
UZ600  -  [G9141P11U_SO8]  258.76 50.76 180 bottom
YA2  -  [Y_X3G024000DC1H_4P]  26.82 21.11 180 top
YH1  -  [Y_FC-135_2P]  278.37 19.44 180 top
YH2  -  [Y_X3G025000DA1H_4P]  261.4 46.52 0 bottom
YV1  -  [Y_X3G025000DI1H-H_4P]  227.22 71.36 180 bottom

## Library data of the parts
ADP100 = ACES_50290-00701-001_7P-T
BAT100 = ACES_50290-01201-P01_12P-T
C1-C6 = C_0402: room: TPM
C8 C13-C18 C37 C38 C42 C43 C47 C48 C53 C54 C56 C57 C59 C93 C1135 C2020 C2021 CA4 CA6 CA7 CA9 CA10 CA13 CA15 CA17 CA19 CA20 CA22-CA25 CA27-CA30 CA32-CA34 CA37-CA39 CA41 CA42 CA53 CA58-CA60 CA63 CA65 CA77 CA79-CA81 CA83 CA87 CA89 CA91-CA97 CE15 CE20 CE23 CE26-CE53 CE58 CH1 CH2 CH13 CH14 CH23-CH26 CH29-CH32 CH40-CH44 CH98-CH101 CH103-CH111 CI5 CI6 CI11-CI13 CI20 CI24 CI26 CI27 CI50 CM22 CM30 CM31 CM33 CN18 CN19 CN28 CN29 CT21 CT44 CU36 CV32 CV639 CV693 CV700 CV701 CV703-CV708 CV710-CV713 CV718 CV725 CV726 CV728-CV733 CV735-CV738 CV743-CV745 CV753 CV754 CV756 CV768 CV771-CV778 CV789 CV795 CV796 CV812 CV813 CV3501 CV3509 CV3512 CZ8 CZ602 PC100-PC107 PC109-PC111 PC120 PC121 PC130 PC200 PC202 PC203 PC208 PC210 PC211 PC213 PC218-PC220 PC225-PC228 PC250-PC252 PC260 PC270 PC271 PC301-PC304 PC306 PC308 PC314 PC315 PC320 PC340 PC402 PC403 PC411 PC412 PC500 PC501 PC509-PC511 PC600-PC602 PC605 PC620 PC704 PC705 PC709 PC710 PC718 PC719 PC721 PC722 PC724-PC726 PC729 PC732-PC734 PC736-PC738 PC761 PC762 PC805-PC807 PC810-PC812 PC818-PC821 PC824 PC825 PC836 PC837 PC850-PC852 PC900-PC909 PC926-PC939 PC991-PC1002 = C_0402
